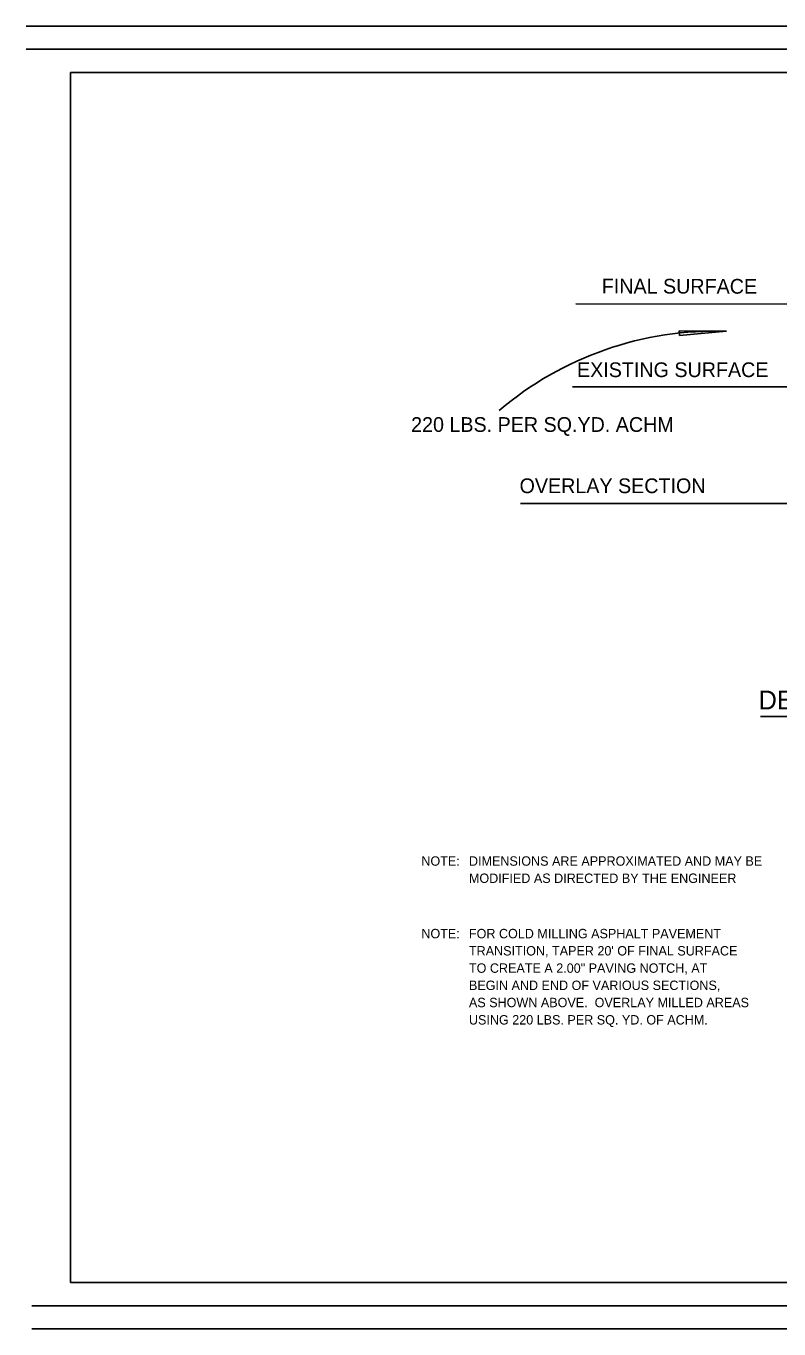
# Model space of a CAD drawing. Extents: x 1944905 to 1956777, y 763871 to 764977.
# Drawn here: x 1951740 to 1952380, y 763871 to 764977 of the extents above; entities that cross this region are included whole.
import ezdxf

# ---------------------------------------------------------------- set-up
doc = ezdxf.new("R2010")
doc.units = 0
for name, color, linetype in [('Default', 7, 'Continuous'), ('R_Border', 7, 'Continuous'), ('R_Dimension', 7, 'Continuous')]:
    doc.layers.add(name, color=color, linetype=linetype)

# ---------------------------------------------------------------- blocks, each defined once
blk = doc.blocks.new('AHD')
at = {"layer": 'R_Dimension'}
for p, q in [((0, 0), (0.796, 1.837)), ((0.975, 1.749), (0, 0)), ((0.796, 1.837), (0.975, 1.749)), ((0.978, 1.754), (0.975, 1.749))]:
    blk.add_line(p, q, dxfattribs=at)

msp = doc.modelspace()

# ---------------------------------------------------------------- linework, layer by layer
at = {"layer": 'Default'}
for p, q in [((1953358.8, 764976.7), (1951740.1, 764976.7)), ((1953358.8, 764957), (1951740.1, 764957)), ((1951777.9, 764937.3), (1953358.8, 764937.3)), ((1951777.9, 763910.1), (1951777.9, 764937.3)), ((1953358.8, 763910.1), (1951777.9, 763910.1)), ((1951745.1, 763890.4), (1953358.8, 763890.4)), ((1951745.1, 763870.7), (1953358.8, 763870.7))]:
    msp.add_line(p, q, dxfattribs=at)
at = {"layer": 'R_Dimension'}
for p, q in [((1952207.1, 764741), (1952401.2, 764740.7)), ((1952204.3, 764670.5), (1952407.7, 764670.5)), ((1952160, 764571.3), (1952900.7, 764571.3)), ((1952363.9, 764390.7), (1952711, 764390.7))]:
    msp.add_line(p, q, dxfattribs=at)
msp.add_ellipse((1952325.5, 764443.2), major_axis=(-279.6, 0.3), ratio=0.981828, start_param=4.679171, end_param=5.429313, dxfattribs=at)

# ---------------------------------------------------------------- block references
at = {"layer": 'R_Border', "xscale": 20.323922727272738, "yscale": 19.953793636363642, "rotation": 118.930778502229}
msp.add_blockref('AHD', (1952335.1, 764717.6), dxfattribs=at)

# ---------------------------------------------------------------- texts
at = {"layer": 'R_Dimension'}
msp.add_text('FINAL SURFACE', height=12.504, rotation=359.9148, dxfattribs=at).set_placement((1952229.1, 764749.7))
for s, height, p in [('EXISTING SURFACE', 12.504, (1952208.1, 764678.7)), ('220 LBS. PER SQ.YD. ACHM', 12.504, (1952067.2, 764632.2)), ('OVERLAY SECTION', 12.504, (1952159.3, 764580.2)), ('DETAILS FOR COLD MILLING', 15.963, (1952362.4, 764396.6)), ('NOTE: ', 7.98, (1952075.9, 764263.9)), ('DIMENSIONS ARE APPROXIMATED AND MAY BE', 7.982, (1952116.3, 764263.9)), ('MODIFIED AS DIRECTED BY THE ENGINEER', 7.982, (1952116.3, 764249.3)), ('NOTE: ', 7.98, (1952075.9, 764202.3)), ('FOR COLD MILLING ASPHALT PAVEMENT', 7.982, (1952116.3, 764202.3)), ("TRANSITION, TAPER 20' OF FINAL SURFACE", 7.982, (1952116.3, 764187.7)), ('TO CREATE A 2.00" PAVING NOTCH, AT', 7.982, (1952116.3, 764173)), ('BEGIN AND END OF VARIOUS SECTIONS,', 7.982, (1952116.3, 764158.4)), ('AS SHOWN ABOVE.  OVERLAY MILLED AREAS', 7.982, (1952116.3, 764143.8)), ('USING 220 LBS. PER SQ. YD. OF ACHM.', 7.982, (1952116.3, 764129.1))]:
    msp.add_text(s, height=height, dxfattribs=at).set_placement(p)

doc.saveas('drawing.dxf')
